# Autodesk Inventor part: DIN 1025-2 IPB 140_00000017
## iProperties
Created: 2006-02
Part Number: DIN 1025-2 IPB 140_00000017
Material: Default
Document SubType Name: Modeling
Designer: 40664
Manufacturer: Standard
Standards Organization: Custom
Stock Number: DIN 1025-2 IPB 140
Mass: 15507.1 g
Surface Area: 29196.4 cm^2
Volume: 15507.1 cm^3
Density: 1 g/cm^3
G_L: 3750.000 mm
G_W: 140.000 mm
G_H: 140.000 mm
AFG_Item: IPB 140
CSToolsMass: 16.0
CSToolsVolume: 15507088.0
CSToolsArea: 29196.0
Author: 40664
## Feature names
1. AFG_Detailed_DIN 1025-2 IPB 140_00000017 [Extrusion]
2. AFG_Simplified_DIN 1025-2 IPB 140_00000017 [Extrusion]
